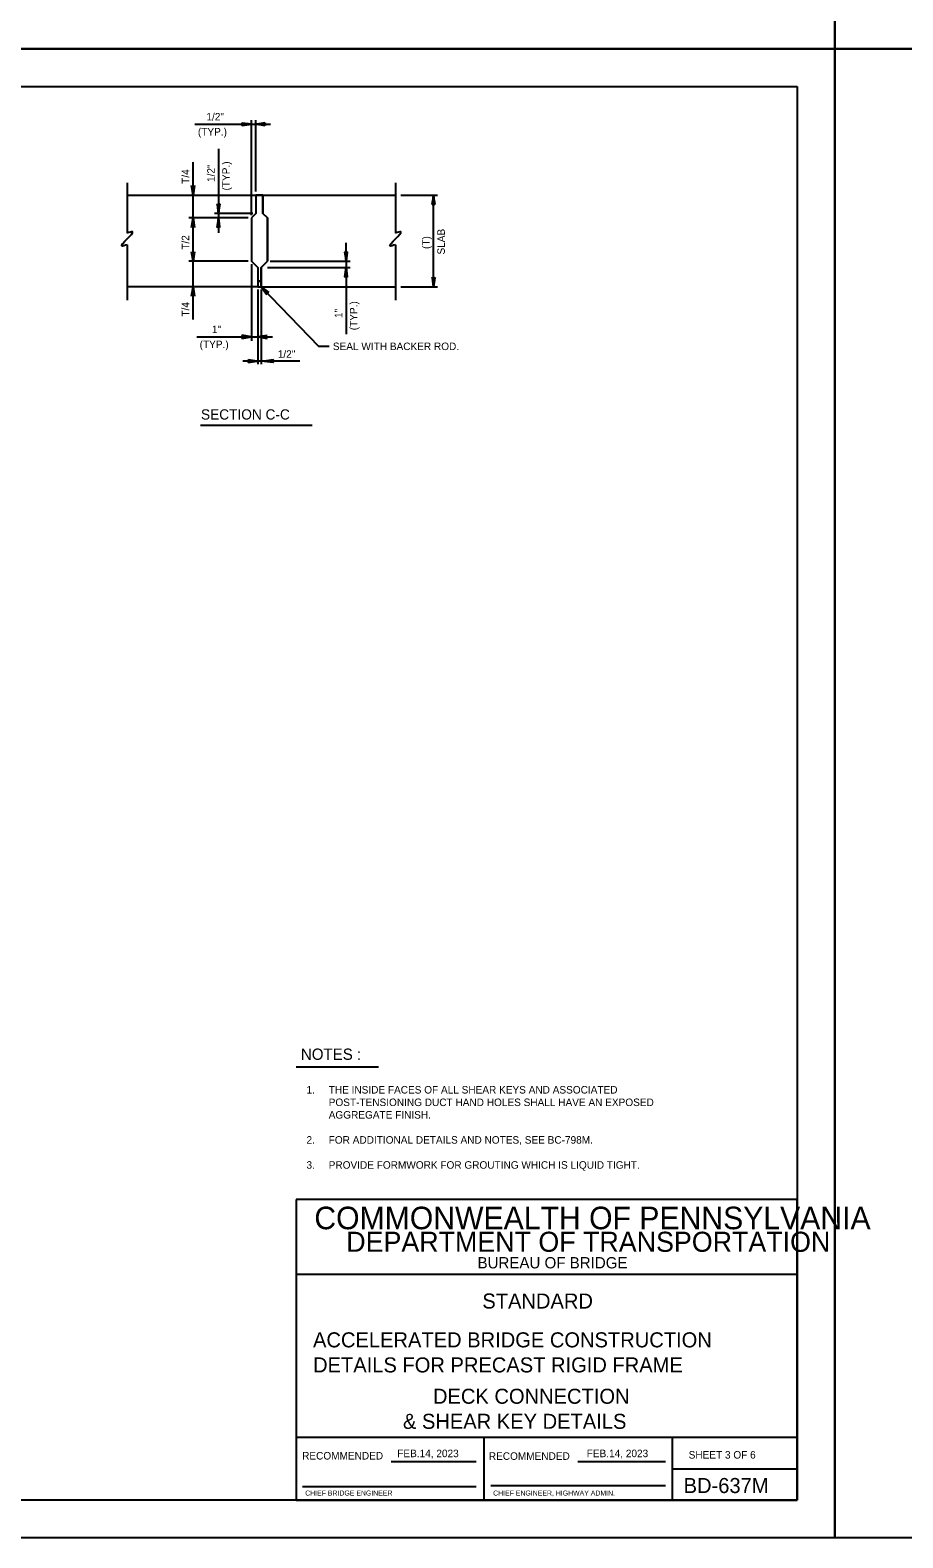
# Model space of a CAD drawing. Extents: x 641328 to 643024, y 298283 to 300065.
# Drawn here: x 641847 to 642196, y 298283 to 298885 of the extents above; entities that cross this region are included whole.
import ezdxf

# ---------------------------------------------------------------- set-up
doc = ezdxf.new("R2010")
doc.units = 0
for name, color, linetype in [('2', 7, 'Continuous'), ('DATES', 7, 'Continuous'), ('Default', 7, 'Continuous'), ('PLT-BNDY', 7, 'Continuous'), ('SIGNATORY TITLES', 7, 'Continuous')]:
    doc.layers.add(name, color=color, linetype=linetype)

msp = doc.modelspace()

# ---------------------------------------------------------------- linework, layer by layer
at = {"layer": '2'}
for p, q in [((641367.51, 298862.3), (642153.5, 298862.3)), ((642153.5, 298862.3), (642153.5, 298298.3)), ((641913.09, 298847.27), (641943.26, 298847.27)), ((641932, 298847.7), (641931.81, 298847.86)), ((641931.81, 298847.86), (641935.61, 298847.27)), ((641935.61, 298847.27), (641931.81, 298846.63)), ((641931.81, 298846.63), (641932.01, 298846.81)), ((641932, 298847.7), (641932.14, 298847.43)), ((641935.61, 298847.27), (641932, 298847.7)), ((641932.01, 298846.81), (641935.61, 298847.27)), ((641932.14, 298847.07), (641932.01, 298846.81)), ((641932.14, 298847.43), (641935.61, 298847.27)), ((641932.14, 298847.43), (641932.14, 298847.07)), ((641935.61, 298847.27), (641932.14, 298847.07)), ((641935.61, 298847.27), (641932.14, 298847.25)), ((641935.61, 298811.03), (641935.61, 298848.89)), ((641937.39, 298820.49), (641937.39, 298848.89)), ((641937.39, 298847.27), (641941.18, 298847.9)), ((641940.99, 298847.72), (641937.39, 298847.27)), ((641937.39, 298847.27), (641940.86, 298847.46)), ((641937.39, 298847.27), (641940.86, 298847.28)), ((641940.86, 298847.1), (641937.39, 298847.27)), ((641937.39, 298847.27), (641941, 298846.84)), ((641941.19, 298846.68), (641937.39, 298847.27)), ((641940.86, 298847.46), (641940.99, 298847.72)), ((641940.86, 298847.1), (641940.86, 298847.46)), ((641941, 298846.84), (641940.86, 298847.1)), ((641941.18, 298847.9), (641940.99, 298847.72)), ((641941, 298846.84), (641941.19, 298846.68)), ((641912.33, 298809.88), (641912.33, 298832.18)), ((641922.5, 298837.48), (641922.5, 298804)), ((641886.04, 298823.86), (641886.04, 298803.82)), ((641912.33, 298819), (641911.69, 298822.8)), ((641911.69, 298822.8), (641911.87, 298822.6)), ((641912.13, 298822.47), (641911.87, 298822.6)), ((641911.87, 298822.6), (641912.33, 298819)), ((641912.33, 298819), (641912.13, 298822.47)), ((641912.49, 298822.47), (641912.13, 298822.47)), ((641912.33, 298819), (641912.31, 298822.47)), ((641912.92, 298822.8), (641912.33, 298819)), ((641912.33, 298819), (641912.76, 298822.61)), ((641912.49, 298822.47), (641912.33, 298819)), ((641912.76, 298822.61), (641912.49, 298822.47)), ((641912.76, 298822.61), (641912.92, 298822.8)), ((641993.09, 298823.86), (641993.09, 298803.82)), ((641886.04, 298819), (641937.39, 298819)), ((641922.07, 298815.26), (641921.91, 298815.46)), ((641921.91, 298815.46), (641922.5, 298811.65)), ((641922.07, 298815.26), (641922.34, 298815.13)), ((641922.5, 298811.65), (641922.07, 298815.26)), ((641922.34, 298815.13), (641922.5, 298811.65)), ((641922.34, 298815.13), (641922.7, 298815.13)), ((641922.5, 298811.65), (641923.14, 298815.45)), ((641922.96, 298815.25), (641922.5, 298811.65)), ((641922.5, 298811.65), (641922.7, 298815.13)), ((641922.5, 298811.65), (641922.52, 298815.13)), ((641922.7, 298815.13), (641922.96, 298815.25)), ((641923.14, 298815.45), (641922.96, 298815.25)), ((641937.39, 298819), (641937.39, 298811.65)), ((641937.39, 298819), (641940.26, 298819)), ((641937.39, 298819), (641937.39, 298811.65)), ((641940.26, 298819), (641993.09, 298819)), ((641940.26, 298819), (641940.26, 298811.65)), ((641940.26, 298811.65), (641940.26, 298819)), ((641995.25, 298819), (642009.96, 298819)), ((642008.34, 298819), (642007.7, 298815.21)), ((642007.7, 298815.21), (642007.88, 298815.4)), ((642007.88, 298815.4), (642008.34, 298819)), ((642008.14, 298815.53), (642007.88, 298815.4)), ((642008.34, 298819), (642008.14, 298815.53)), ((642008.5, 298815.53), (642008.14, 298815.53)), ((642008.34, 298819), (642008.32, 298815.53)), ((642008.34, 298782.43), (642008.34, 298819)), ((642008.5, 298815.53), (642008.34, 298819)), ((642008.34, 298819), (642008.77, 298815.39)), ((642008.93, 298815.2), (642008.34, 298819)), ((642008.77, 298815.39), (642008.5, 298815.53)), ((642008.77, 298815.39), (642008.93, 298815.2)), ((641934.3, 298809.88), (641910.7, 298809.88)), ((641911.74, 298806.07), (641912.33, 298809.88)), ((641912.33, 298809.88), (641911.9, 298806.27)), ((641912.16, 298806.4), (641912.33, 298809.88)), ((641912.33, 298792.58), (641912.33, 298809.88)), ((641912.33, 298809.88), (641912.52, 298806.4)), ((641912.79, 298806.28), (641912.33, 298809.88)), ((641912.33, 298809.88), (641912.96, 298806.08)), ((641912.33, 298809.88), (641912.34, 298806.4)), ((641936.17, 298811.65), (641920.88, 298811.65)), ((641922.5, 298809.88), (641921.87, 298806.08)), ((641922.05, 298806.28), (641922.5, 298809.88)), ((641922.5, 298809.88), (641922.31, 298806.4)), ((641922.5, 298809.88), (641922.49, 298806.4)), ((641922.67, 298806.4), (641922.5, 298809.88)), ((641922.5, 298809.88), (641922.93, 298806.27)), ((641923.09, 298806.07), (641922.5, 298809.88)), ((641937.39, 298811.65), (641935.61, 298809.88)), ((641937.39, 298811.65), (641935.61, 298809.88)), ((641935.61, 298809.88), (641935.61, 298792.58)), ((641935.61, 298809.88), (641935.61, 298792.58)), ((641940.26, 298811.65), (641942.04, 298809.88)), ((641942.04, 298809.88), (641940.26, 298811.65)), ((641942.04, 298809.88), (641942.04, 298792.58)), ((641942.04, 298792.58), (641942.04, 298809.88)), ((641911.9, 298806.27), (641911.74, 298806.07)), ((641911.9, 298806.27), (641912.16, 298806.4)), ((641912.16, 298806.4), (641912.52, 298806.4)), ((641912.52, 298806.4), (641912.79, 298806.28)), ((641912.96, 298806.08), (641912.79, 298806.28)), ((641921.87, 298806.08), (641922.05, 298806.28)), ((641922.31, 298806.4), (641922.05, 298806.28)), ((641922.67, 298806.4), (641922.31, 298806.4)), ((641922.93, 298806.27), (641922.67, 298806.4)), ((641922.93, 298806.27), (641923.09, 298806.07)), ((641886.04, 298799.2), (641886.04, 298777.07)), ((641912.33, 298792.58), (641911.69, 298796.37)), ((641911.69, 298796.37), (641911.87, 298796.18)), ((641912.13, 298796.05), (641911.87, 298796.18)), ((641911.87, 298796.18), (641912.33, 298792.58)), ((641912.33, 298792.58), (641912.13, 298796.05)), ((641912.49, 298796.05), (641912.13, 298796.05)), ((641912.33, 298792.58), (641912.31, 298796.05)), ((641912.92, 298796.38), (641912.33, 298792.58)), ((641912.33, 298792.58), (641912.76, 298796.19)), ((641912.49, 298796.05), (641912.33, 298792.58)), ((641912.76, 298796.19), (641912.49, 298796.05)), ((641912.76, 298796.19), (641912.92, 298796.38)), ((641972.99, 298796.19), (641972.83, 298796.38)), ((641972.83, 298796.38), (641973.42, 298792.58)), ((641972.99, 298796.19), (641973.25, 298796.05)), ((641973.42, 298792.58), (641972.99, 298796.19)), ((641973.25, 298796.05), (641973.42, 298792.58)), ((641973.25, 298796.05), (641973.62, 298796.05)), ((641973.42, 298792.58), (641973.42, 298799.93)), ((641973.42, 298792.58), (641974.05, 298796.37)), ((641973.88, 298796.18), (641973.42, 298792.58)), ((641973.42, 298792.58), (641973.62, 298796.05)), ((641973.42, 298792.58), (641973.43, 298796.05)), ((641973.62, 298796.05), (641973.88, 298796.18)), ((641974.05, 298796.37), (641973.88, 298796.18)), ((641993.09, 298799.2), (641993.09, 298777.07)), ((641934.3, 298792.58), (641910.7, 298792.58)), ((641912.33, 298769.31), (641912.33, 298792.58)), ((641938.14, 298790.05), (641935.61, 298792.58)), ((641935.61, 298792.58), (641938.14, 298790.05)), ((641935.61, 298791.43), (641935.61, 298760.8)), ((641938.14, 298790.05), (641938.14, 298782.43)), ((641938.14, 298790.05), (641938.14, 298784.61)), ((641939.51, 298790.05), (641942.04, 298792.58)), ((641939.51, 298790.05), (641942.04, 298792.58)), ((641939.51, 298790.05), (641939.51, 298782.43)), ((641939.51, 298784.61), (641939.51, 298790.05)), ((641942.11, 298790.05), (641975.04, 298790.05)), ((641943.09, 298792.58), (641975.04, 298792.58)), ((641973.42, 298790.05), (641972.78, 298786.26)), ((641972.96, 298786.45), (641973.42, 298790.05)), ((641973.42, 298790.05), (641973.22, 298786.58)), ((641973.42, 298790.05), (641973.4, 298786.58)), ((641973.42, 298792.58), (641973.42, 298763.53)), ((641973.59, 298786.58), (641973.42, 298790.05)), ((641973.42, 298790.05), (641973.85, 298786.44)), ((641974.01, 298786.25), (641973.42, 298790.05)), ((641938.14, 298784.61), (641939.51, 298784.61)), ((641972.78, 298786.26), (641972.96, 298786.45)), ((641973.22, 298786.58), (641972.96, 298786.45)), ((641973.59, 298786.58), (641973.22, 298786.58)), ((641973.85, 298786.44), (641973.59, 298786.58)), ((641973.85, 298786.44), (641974.01, 298786.25)), ((642007.9, 298786.03), (642007.74, 298786.23)), ((642007.74, 298786.23), (642008.34, 298782.43)), ((642007.9, 298786.03), (642008.17, 298785.9)), ((642008.34, 298782.43), (642007.9, 298786.03)), ((642008.17, 298785.9), (642008.34, 298782.43)), ((642008.17, 298785.9), (642008.53, 298785.9)), ((642008.34, 298782.43), (642008.97, 298786.22)), ((642008.79, 298786.02), (642008.34, 298782.43)), ((642008.34, 298782.43), (642008.53, 298785.9)), ((642008.34, 298782.43), (642008.35, 298785.9)), ((642008.53, 298785.9), (642008.79, 298786.02)), ((642008.97, 298786.22), (642008.79, 298786.02)), ((641938.14, 298782.43), (641886.04, 298782.43)), ((641911.74, 298778.62), (641912.33, 298782.43)), ((641911.9, 298778.82), (641911.74, 298778.62)), ((641912.33, 298782.43), (641911.9, 298778.82)), ((641911.9, 298778.82), (641912.16, 298778.95)), ((641912.16, 298778.95), (641912.33, 298782.43)), ((641912.16, 298778.95), (641912.52, 298778.95)), ((641912.33, 298782.43), (641912.52, 298778.95)), ((641912.79, 298778.83), (641912.33, 298782.43)), ((641912.33, 298782.43), (641912.96, 298778.63)), ((641912.33, 298782.43), (641912.34, 298778.95)), ((641912.52, 298778.95), (641912.79, 298778.83)), ((641912.96, 298778.63), (641912.79, 298778.83)), ((641938.14, 298782.43), (641939.51, 298782.43)), ((641938.14, 298781.31), (641938.14, 298751.5)), ((641939.51, 298782.43), (641993.09, 298782.43)), ((641939.51, 298782.43), (641962.41, 298758.67)), ((641941.8, 298779.81), (641939.51, 298782.43)), ((641939.51, 298782.43), (641941.71, 298779.53)), ((641941.73, 298779.28), (641939.51, 298782.43)), ((641939.51, 298782.43), (641942.06, 298780.06)), ((641942.34, 298780.15), (641939.51, 298782.43)), ((641939.51, 298782.43), (641942.6, 298780.13)), ((641939.51, 298782.43), (641941.93, 298779.94)), ((641939.51, 298781.27), (641939.51, 298763.02)), ((641941.71, 298779.53), (641941.8, 298779.81)), ((641941.71, 298779.53), (641941.73, 298779.28)), ((641941.8, 298779.81), (641942.06, 298780.06)), ((641942.06, 298780.06), (641942.34, 298780.15)), ((641942.6, 298780.13), (641942.34, 298780.15)), ((641995.25, 298782.43), (642009.96, 298782.43)), ((641913.84, 298762.43), (641944.01, 298762.43)), ((641935.61, 298762.43), (641931.81, 298763.06)), ((641931.81, 298763.06), (641932.01, 298762.88)), ((641931.81, 298761.84), (641935.61, 298762.43)), ((641932, 298762), (641931.81, 298761.84)), ((641935.61, 298762.43), (641932, 298762)), ((641932, 298762), (641932.14, 298762.26)), ((641932.14, 298762.62), (641932.01, 298762.88)), ((641932.01, 298762.88), (641935.61, 298762.43)), ((641935.61, 298762.43), (641932.14, 298762.62)), ((641932.14, 298762.26), (641932.14, 298762.62)), ((641935.61, 298762.43), (641932.14, 298762.44)), ((641932.14, 298762.26), (641935.61, 298762.43)), ((641941.94, 298763.02), (641938.14, 298762.43)), ((641938.14, 298762.43), (641941.75, 298762.86)), ((641941.61, 298762.59), (641938.14, 298762.43)), ((641938.14, 298762.43), (641941.61, 298762.23)), ((641941.74, 298761.97), (641938.14, 298762.43)), ((641938.14, 298762.43), (641941.93, 298761.79)), ((641938.14, 298762.43), (641941.61, 298762.41)), ((641939.51, 298761.79), (641939.51, 298751.5)), ((641941.75, 298762.86), (641941.61, 298762.59)), ((641941.61, 298762.59), (641941.61, 298762.23)), ((641941.61, 298762.23), (641941.74, 298761.97)), ((641941.93, 298761.79), (641941.74, 298761.97)), ((641941.75, 298762.86), (641941.94, 298763.02)), ((641934.53, 298753.2), (641934.34, 298753.36)), ((641934.34, 298753.36), (641938.14, 298752.77)), ((641940.67, 298752.77), (641944.46, 298753.4)), ((641944.46, 298753.4), (641944.26, 298753.23)), ((641962.41, 298758.67), (641966.69, 298758.67)), ((641955.03, 298752.77), (641932.27, 298752.77)), ((641938.14, 298752.77), (641934.34, 298752.13)), ((641934.34, 298752.13), (641934.54, 298752.31)), ((641934.53, 298753.2), (641934.66, 298752.93)), ((641938.14, 298752.77), (641934.53, 298753.2)), ((641934.54, 298752.31), (641938.14, 298752.77)), ((641934.67, 298752.57), (641934.54, 298752.31)), ((641934.66, 298752.93), (641938.14, 298752.77)), ((641934.66, 298752.93), (641934.67, 298752.57)), ((641938.14, 298752.77), (641934.67, 298752.57)), ((641938.14, 298752.77), (641934.67, 298752.75)), ((641944.26, 298753.23), (641940.67, 298752.77)), ((641940.67, 298752.77), (641944.14, 298752.96)), ((641940.67, 298752.77), (641944.14, 298752.78)), ((641944.14, 298752.6), (641940.67, 298752.77)), ((641940.67, 298752.77), (641944.28, 298752.34)), ((641944.47, 298752.18), (641940.67, 298752.77)), ((641944.14, 298752.96), (641944.26, 298753.23)), ((641944.14, 298752.6), (641944.14, 298752.96)), ((641944.28, 298752.34), (641944.14, 298752.6)), ((641944.28, 298752.34), (641944.47, 298752.18)), ((641953.46, 298471.22), (641986.34, 298471.22)), ((642153.5, 298418.3), (641953.5, 298418.3)), ((641953.5, 298418.3), (641953.5, 298298.3)), ((642153.5, 298298.3), (642153.5, 298418.3)), ((642153.5, 298388.3), (641953.5, 298388.3)), ((642153.5, 298323.3), (641953.5, 298323.3)), ((642028.5, 298298.3), (642028.5, 298323.3)), ((642103.5, 298323.3), (642103.5, 298298.3)), ((641991.35, 298313.8), (642025.39, 298313.8)), ((642065.95, 298313.8), (642100.92, 298313.8)), ((642103.5, 298310.8), (642153.5, 298310.8)), ((641956, 298303.8), (642025.39, 298303.8)), ((642031.13, 298304.17), (642100.92, 298304.17)), ((642153.5, 298298.3), (641367.51, 298298.3)), ((641953.5, 298298.3), (642153.5, 298298.3))]:
    msp.add_line(p, q, dxfattribs=at)
msp.add_lwpolyline([(641940.26, 298819), (641938.83, 298819), (641937.39, 298819)], dxfattribs=at)
msp.add_lwpolyline([(641938.14, 298782.43), (641939.51, 298782.43), (641939.51, 298784.61), (641938.14, 298784.61)], close=True, dxfattribs=at)
for points in [[(641886.04, 298799.2), (641883.91, 298798.7), (641888.16, 298804.32), (641886.04, 298803.82)], [(641993.09, 298799.2), (641990.96, 298798.7), (641995.21, 298804.32), (641993.09, 298803.82)]]:
    msp.add_spline(points, degree=3, dxfattribs=at)
at = {"layer": 'Default'}
msp.add_line((641915.27, 298727.15), (641959.87, 298727.15), dxfattribs=at)
at = {"layer": 'PLT-BNDY'}
for points in [[(641327.51, 299471.3), (642168.51, 299471.3), (642168.51, 298877.3), (641327.51, 298877.3)], [(642168.51, 299471.3), (643009.51, 299471.3), (643009.51, 298877.3), (642168.51, 298877.3)], [(641327.51, 298877.3), (642168.51, 298877.3), (642168.51, 298283.3), (641327.51, 298283.3)], [(642168.51, 298877.3), (643009.51, 298877.3), (643009.51, 298283.3), (642168.51, 298283.3)]]:
    msp.add_lwpolyline(points, close=True, dxfattribs=at)

# ---------------------------------------------------------------- texts
at = {"layer": '2'}
for s, height, p in [('1/2"', 3, (641917.68, 298848.77)), ('(TYP.)', 3, (641914.29, 298842.77)), ('1"', 3, (641919.87, 298763.93)), ('(TYP.)', 3, (641914.98, 298757.93)), ('SEAL WITH BACKER ROD.', 3, (641968.15, 298757.16)), ('1/2"', 3, (641946.17, 298754.08)), ('NOTES : ', 4.5, (641955.38, 298474)), ('1.', 3, (641957.62, 298460.56)), ('THE INSIDE FACES OF ALL SHEAR KEYS AND ASSOCIATED ', 3, (641966.49, 298460.56)), ('POST-TENSIONING DUCT HAND HOLES SHALL HAVE AN EXPOSED ', 3, (641966.49, 298455.56)), ('AGGREGATE FINISH.', 3, (641966.49, 298450.56)), ('2.', 3, (641957.62, 298440.56)), ('FOR ADDITIONAL DETAILS AND NOTES, SEE BC-798M.', 3, (641966.49, 298440.56)), ('3.', 3, (641957.62, 298430.56)), ('PROVIDE FORMWORK FOR GROUTING WHICH IS LIQUID TIGHT.', 3, (641966.49, 298430.56)), ('COMMONWEALTH OF PENNSYLVANIA', 9, (641960.75, 298406.42)), ('DEPARTMENT OF TRANSPORTATION', 8.0002, (641973.5, 298397.42)), ('BUREAU OF BRIDGE', 4.5, (642025.88, 298390.8)), ('STANDARD', 6, (642027.8, 298374.78)), ('ACCELERATED BRIDGE CONSTRUCTION', 6, (641960.23, 298359.29)), ('DETAILS FOR PRECAST RIGID FRAME', 6, (641960.25, 298349.29)), ('DECK CONNECTION ', 6, (642008.1, 298336.79)), ('& SHEAR KEY DETAILS', 6, (641996.12, 298326.79)), ('SHEET 3 OF 6', 3, (642110.14, 298314.92)), ('BD-637M', 6, (642108.13, 298301.17))]:
    msp.add_text(s, height=height, dxfattribs=at).set_placement(p)
for s, rotation, p in [('(TYP.)', 90, (641927, 298820.84)), ('T/4', 90, (641910.84, 298823.5)), ('1/2"', 90, (641921, 298824.23)), ('T/2', 90, (641910.84, 298797.2)), ('(T)', 90, (642006.84, 298797.48)), ('SLAB', 90, (642012.84, 298795.28)), ('T/4', 90, (641910.84, 298770.5)), ('1"', 90, (641971.92, 298769.95)), ('(TYP.)', 90, (641977.92, 298765.07)), ('RECOMMENDED', 360, (641955.88, 298314.55)), ('RECOMMENDED', 360, (642030.39, 298314.42))]:
    msp.add_text(s, height=3, rotation=rotation, dxfattribs=at).set_placement(p)
at = {"layer": 'DATES'}
for p in [(641993.84, 298315.48), (642069.46, 298315.48)]:
    msp.add_text('FEB.14, 2023', height=3, dxfattribs=at).set_placement(p)
at = {"layer": 'Default'}
msp.add_text('SECTION C-C', height=4.08, dxfattribs=at).set_placement((641915.52, 298729.45))
at = {"layer": 'SIGNATORY TITLES'}
for s, p in [('CHIEF BRIDGE ENGINEER', (641957.1, 298300.17)), ('CHIEF ENGINEER, HIGHWAY ADMIN.', (642032.1, 298300.17))]:
    msp.add_text(s, height=2, dxfattribs=at).set_placement(p)

doc.saveas('drawing.dxf')
